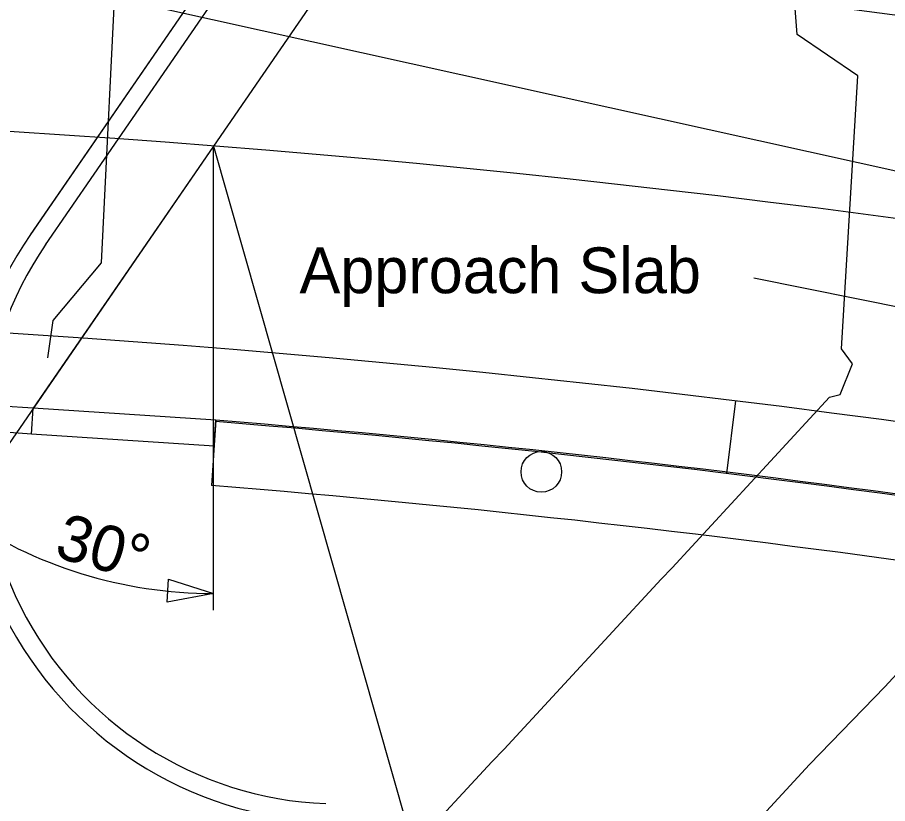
# Model space of a CAD drawing. Extents: x 1385284 to 1385995, y 1975154 to 1975620.
# Drawn here: x 1385558.27 to 1385605.82, y 1975451.48 to 1975494.43 of the extents above; entities that cross this region are included whole.
import ezdxf

# ---------------------------------------------------------------- set-up
doc = ezdxf.new("R2010")
doc.units = 0
for name, color, linetype in [('B-Super-Deck', 7, 'Continuous'), ('Default', 7, 'Continuous'), ('DTM CONTOURS_MAJOR', 7, 'Continuous'), ('DTM_CONTOURS_MINOR', 7, 'Continuous'), ('R_Bridge', 7, 'Continuous'), ('R_Guardrail', 7, 'Continuous'), ('R_Horz Alg', 7, 'Continuous'), ('R_Horz Alg Annot', 7, 'Continuous'), ('R_Proposed Const Limits', 7, 'Continuous'), ('R_Proposed Road', 7, 'Continuous'), ('R_Shld', 7, 'Continuous')]:
    doc.layers.add(name, color=color, linetype=linetype)

msp = doc.modelspace()

# ---------------------------------------------------------------- linework, layer by layer
at = {"layer": 'B-Super-Deck'}
for p, q in [((1385569.115, 1975472.424), (1385559.137, 1975473.083)), ((1385569.033, 1975471.177), (1385569.115, 1975472.424)), ((1385569.022, 1975471.011), (1385559.043, 1975471.67))]:
    msp.add_line(p, q, dxfattribs=at)
at = {"layer": 'Default'}
for p, q in [((1385601.664, 1975544.642), (1385558.992, 1975482.58)), ((1385559.816, 1975482.013), (1385602.488, 1975544.075)), ((1385574.233, 1975504.747), (1385558.972, 1975482.551)), ((1385568.987, 1975487.408), (1385554.822, 1975466.808)), ((1385568.987, 1975487.408), (1385600.804, 1975375.659)), ((1385568.987, 1975462.047), (1385568.987, 1975487.408)), ((1385598.514, 1975480.21), (1385610.757, 1975477.735))]:
    msp.add_line(p, q, dxfattribs=at)
msp.add_lwpolyline([(1385566.529, 1975463.736), (1385568.987, 1975462.959), (1385566.453, 1975462.488)], close=True, dxfattribs=at)
for centre, radius, start, end in [((1385575.884, 1975470.965), 35, 144.0867, 263.6071), ((1385575.884, 1975470.965), 34, 144.0867, 263.6071), ((1385575.884, 1975470.965), 20.5, 145.4884, 267.767), ((1385575.884, 1975470.965), 19.5, 145.3879, 267.767), ((1385568.987, 1975487.408), 24.449, 235.4884, 270)]:
    msp.add_arc(centre, radius, start, end, dxfattribs=at)
at = {"layer": 'DTM CONTOURS_MAJOR'}
msp.add_lwpolyline([(1385567.349, 1975435.532), (1385575.643, 1975444.505), (1385584.2, 1975453.764), (1385584.866, 1975454.455), (1385593.445, 1975463.74), (1385594.049, 1975464.365), (1385602.648, 1975473.677), (1385603.227, 1975473.83), (1385603.894, 1975475.512), (1385603.308, 1975476.333), (1385604.191, 1975491.234), (1385600.884, 1975493.495), (1385599.902, 1975506.35), (1385595.893, 1975509.526), (1385591.739, 1975515.976)], dxfattribs=at)
at = {"layer": 'DTM_CONTOURS_MINOR'}
for points in [[(1385579.367, 1975429.786), (1385585.057, 1975435.943), (1385591.289, 1975442.686), (1385595.354, 1975446.898), (1385601.553, 1975453.608), (1385605.67, 1975457.865), (1385611.834, 1975464.54), (1385616.326, 1975465.731), (1385621.494, 1975478.78), (1385616.95, 1975485.142), (1385617.369, 1975492.225), (1385607.301, 1975499.112)], [(1385559.944, 1975475.839), (1385560.221, 1975477.867), (1385562.866, 1975481.018), (1385563.716, 1975498.339)]]:
    msp.add_lwpolyline(points, dxfattribs=at)
at = {"layer": 'R_Bridge'}
for p in [(1385578.766, 1975501.631), (1385559.043, 1975471.67)]:
    msp.add_line(p, (1385559.137, 1975473.083), dxfattribs=at)
for radius in [679.494, 678.078]:
    msp.add_arc((1385514.357, 1974795.066), radius, 86.221345, 95.633125, dxfattribs=at)
at = {"layer": 'R_Guardrail'}
msp.add_circle((1385586.901, 1975469.605), 1.109, dxfattribs=at)
msp.add_arc((1385514.472, 1974795.13), 679.494, 81.777396, 85.387485, dxfattribs=at)
at = {"layer": 'R_Horz Alg'}
msp.add_arc((1385514.357, 1974795.066), 694.494, 77.498258, 106.635112, dxfattribs=at)
at = {"layer": 'R_Horz Alg Annot'}
msp.add_line((1385315.54, 1975550.51), (1385664.693, 1975473.094), dxfattribs=at)
at = {"layer": 'R_Proposed Const Limits'}
msp.add_arc((1385575.884, 1975470.965), 30, 145.4884, 267.767, dxfattribs=at)
at = {"layer": 'R_Proposed Road'}
msp.add_line((1385597.038, 1975469.511), (1385597.525, 1975473.482), dxfattribs=at)
for radius, end in [(705.494, 106.368381), (683.494, 106.910819)]:
    msp.add_arc((1385514.357, 1974795.066), radius, 77.498258, end, dxfattribs=at)
at = {"layer": 'R_Shld'}
msp.add_line((1385569.115, 1975472.424), (1385568.88, 1975468.858), dxfattribs=at)
for radius, start, end in [(709.494, 77.498258, 83.983855), (679.494, 77.498258, 85.378103), (675.994, 81.768466, 85.373737)]:
    msp.add_arc((1385514.357, 1974795.066), radius, start, end, dxfattribs=at)

# ---------------------------------------------------------------- texts
at = {"layer": 'Default'}
msp.add_text('Approach Slab', height=2.49999, dxfattribs=at).set_placement((1385573.688, 1975479.366))
msp.add_text('30%%d', height=2.5, rotation=344.2207, dxfattribs=at).set_placement((1385560.216, 1975464.98))

doc.saveas('drawing.dxf')
